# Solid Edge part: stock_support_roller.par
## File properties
Accuracy: 0.99
Title: Stock support roller
Author: Abhinav Rai
Template: Normal.par
Last saved by: CADCIM
Revision: 13
Application: Solid Edge
Material: aluminum
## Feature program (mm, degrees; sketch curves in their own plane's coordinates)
sketch for "unnamed RevolvedProtrusion 1" plane through (0, 0, 0) normal (0, -1, 0) x-axis (1, 0, 0)
  line (60, 0) -> (60, 18.669)
  line (60, 18.669) -> (15.55, 18.669)
  line (15.55, 18.669) -> (15.55, 92.075)
  line (15.55, 92.075) -> (-2.2388, 92.075)
  line (-2.2388, 92.075) -> (-111.45, 29.0219)
  line (-220.6612, 92.075) -> (-111.45, 29.0219)
  line (-238.45, 92.075) -> (-220.6612, 92.075)
  line (-238.45, 18.669) -> (-238.45, 92.075)
  line (-282.9, 18.669) -> (-238.45, 18.669)
  line (-282.9, 0) -> (-282.9, 18.669)
revolve "unnamed RevolvedProtrusion 1" add full turn 360 deg about sketch line (-282.9, 0) -> (60, 0)
chamfer "unnamed Chamfer 1"
fillet "Round_1" radius 1.5748
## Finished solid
Body 1: solid body, 14 faces, 13 edges, 0 vertices.
  Faces by surface: cone 4, cylinder 4, plane 4, torus 2
  Edges by curve: circle 13
Bounding box of the edges (mm; curved faces can reach further): 342.900 x 184.150 x 184.150, from (-282.9, -92.075, -92.075) to (60, 92.075, 92.075).
Cylindrical faces by radius (mm): R18.669 x2, R92.075 x2
Conical faces (half-angle, radius in mm at the cone's reference point): 30 deg R29.0219 x1, 30 deg R92.075 x1, 45 deg R17.0942 x1, 45 deg R18.669 x1
Toroidal faces (ring radius, tube radius in mm): R20.2438 r1.5748 x2
Planar faces by outward normal: +x 2, -x 2
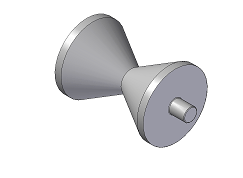
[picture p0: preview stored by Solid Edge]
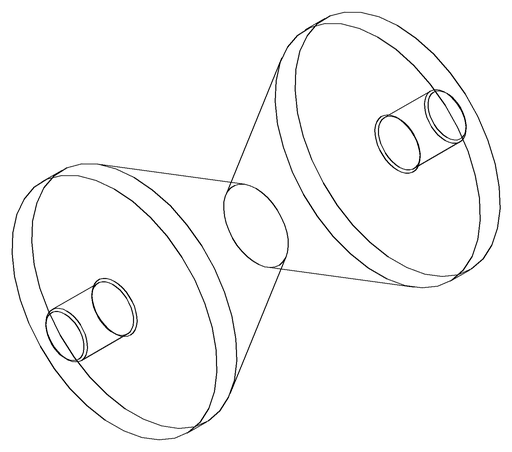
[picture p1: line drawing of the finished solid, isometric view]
